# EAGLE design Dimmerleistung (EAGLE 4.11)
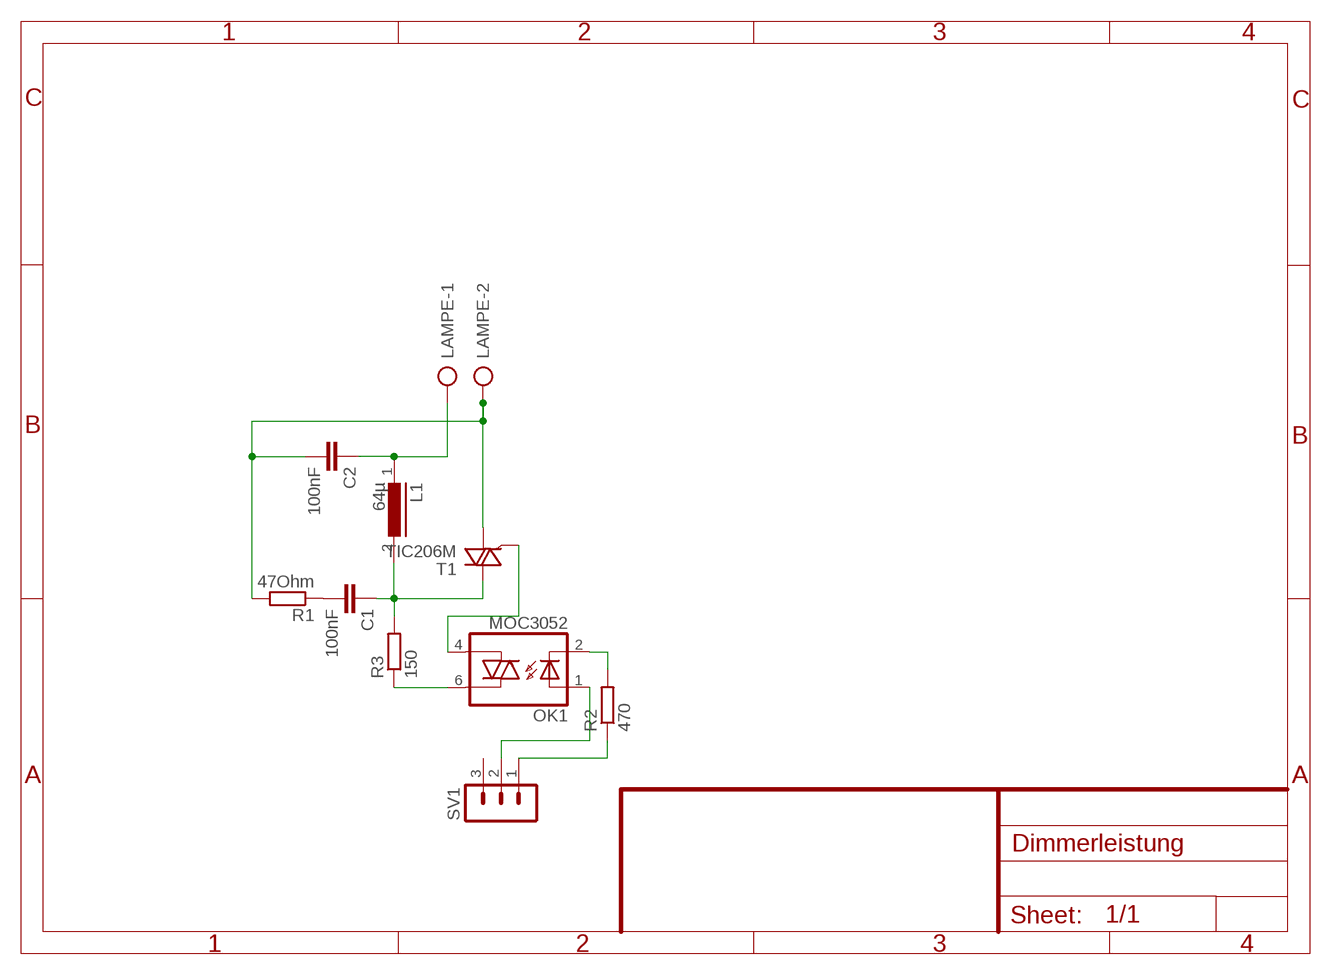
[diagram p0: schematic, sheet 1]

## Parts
C1  100nF  C-EU075-032X103  [C075-032X103]
C2  100nF  C-EU075-032X103  [C075-032X103]
L1  64µ  SFT830D  [SFT830D]
LAMPE  AK300/2  [AK300/2]
OK1  MOC3052  IL420  [DIL06]
R1  47Ohm  R-EU_0207/10  [0207/10]
R2  470  R-EU_0207/10  [0207/10]
R3  150  R-EU_0207/10  [0207/10]
SV1  MA03-1  [MA03-1]
T1  TIC206M  TIC225S  [TO220DS]

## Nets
N$1: OK1.4(A1) T1.G
N$2: C1.2 R1.1
N$3: C1.1 L1.2 R3.2 T1.A2
N$4: C2.1 L1.1 LAMPE.1
N$7: OK1.1(A) SV1.2
N$8: R2.1 SV1.1
N$9: OK1.2(C) R2.2
N$10: OK1.6(A2) R3.1
N$11: C2.2 LAMPE.2 R1.2 T1.A1
Unconnected: SV1.3

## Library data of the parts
C1 C2 = rcl:C-EU: CAPACITOR, European symbol
L1 = inductors:SFT830D: INDUCTOR
LAMPE = con-ptr500:AK300/2: CONNECTOR
OK1 = optocoupler:IL420: SIEMENS OPTO COUPLER
R1-R3 = rcl:R-EU_: RESISTOR, European symbol
SV1 = con-lstb:MA03-1: PIN HEADER
T1 = triac:TIC225S: TRIAC

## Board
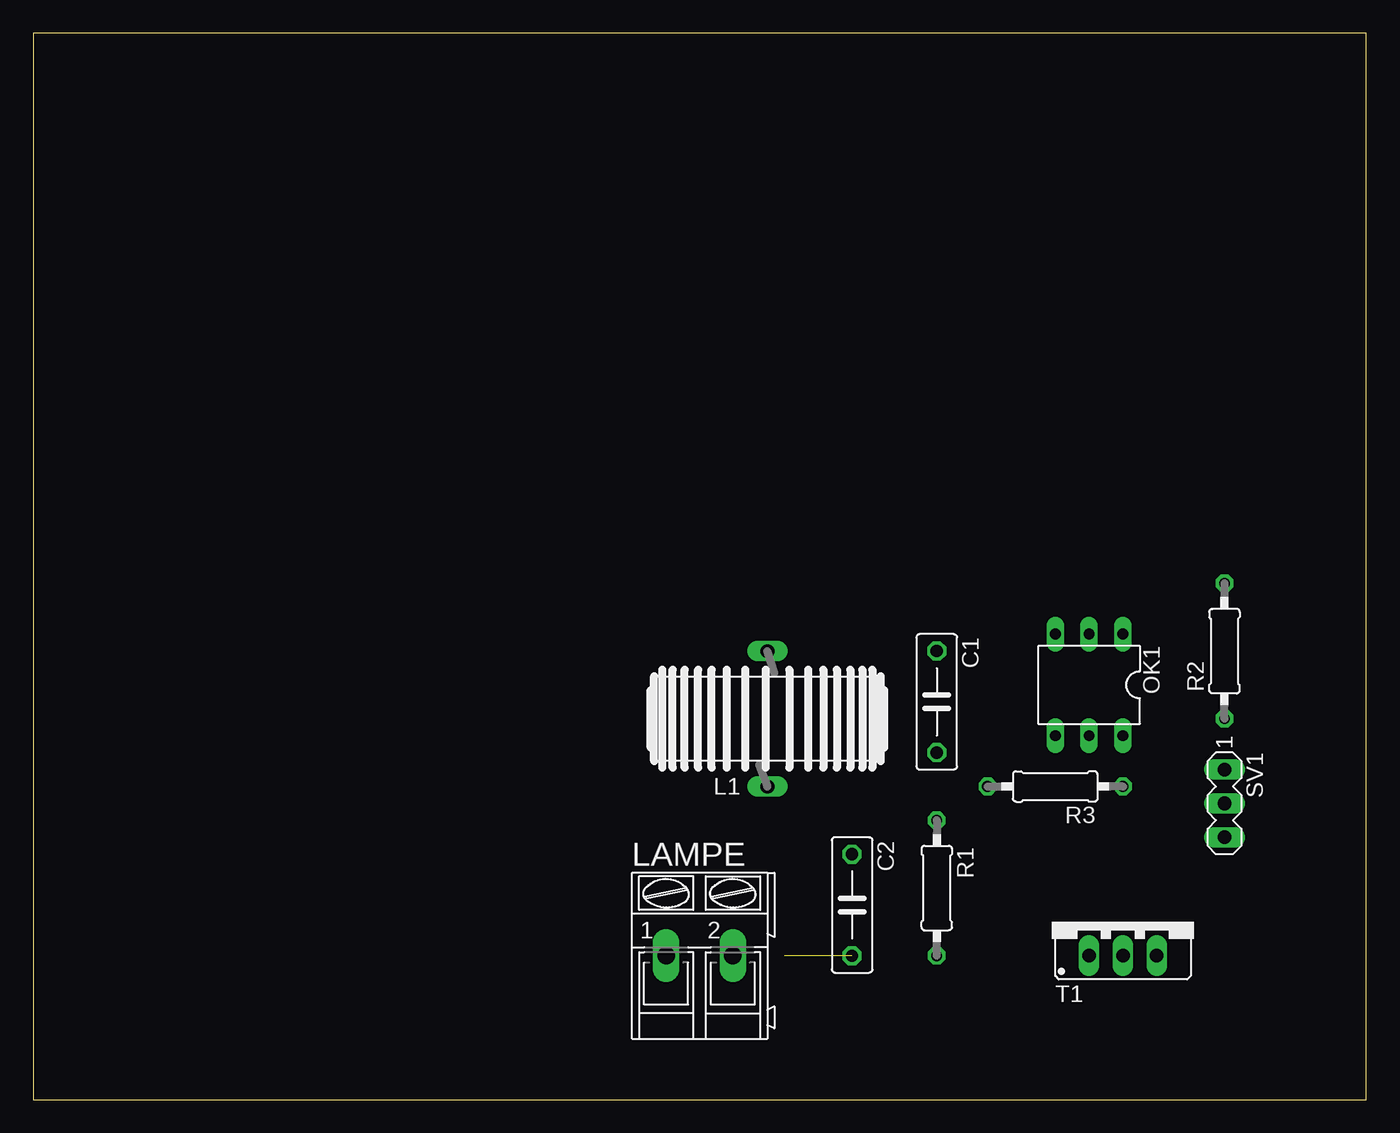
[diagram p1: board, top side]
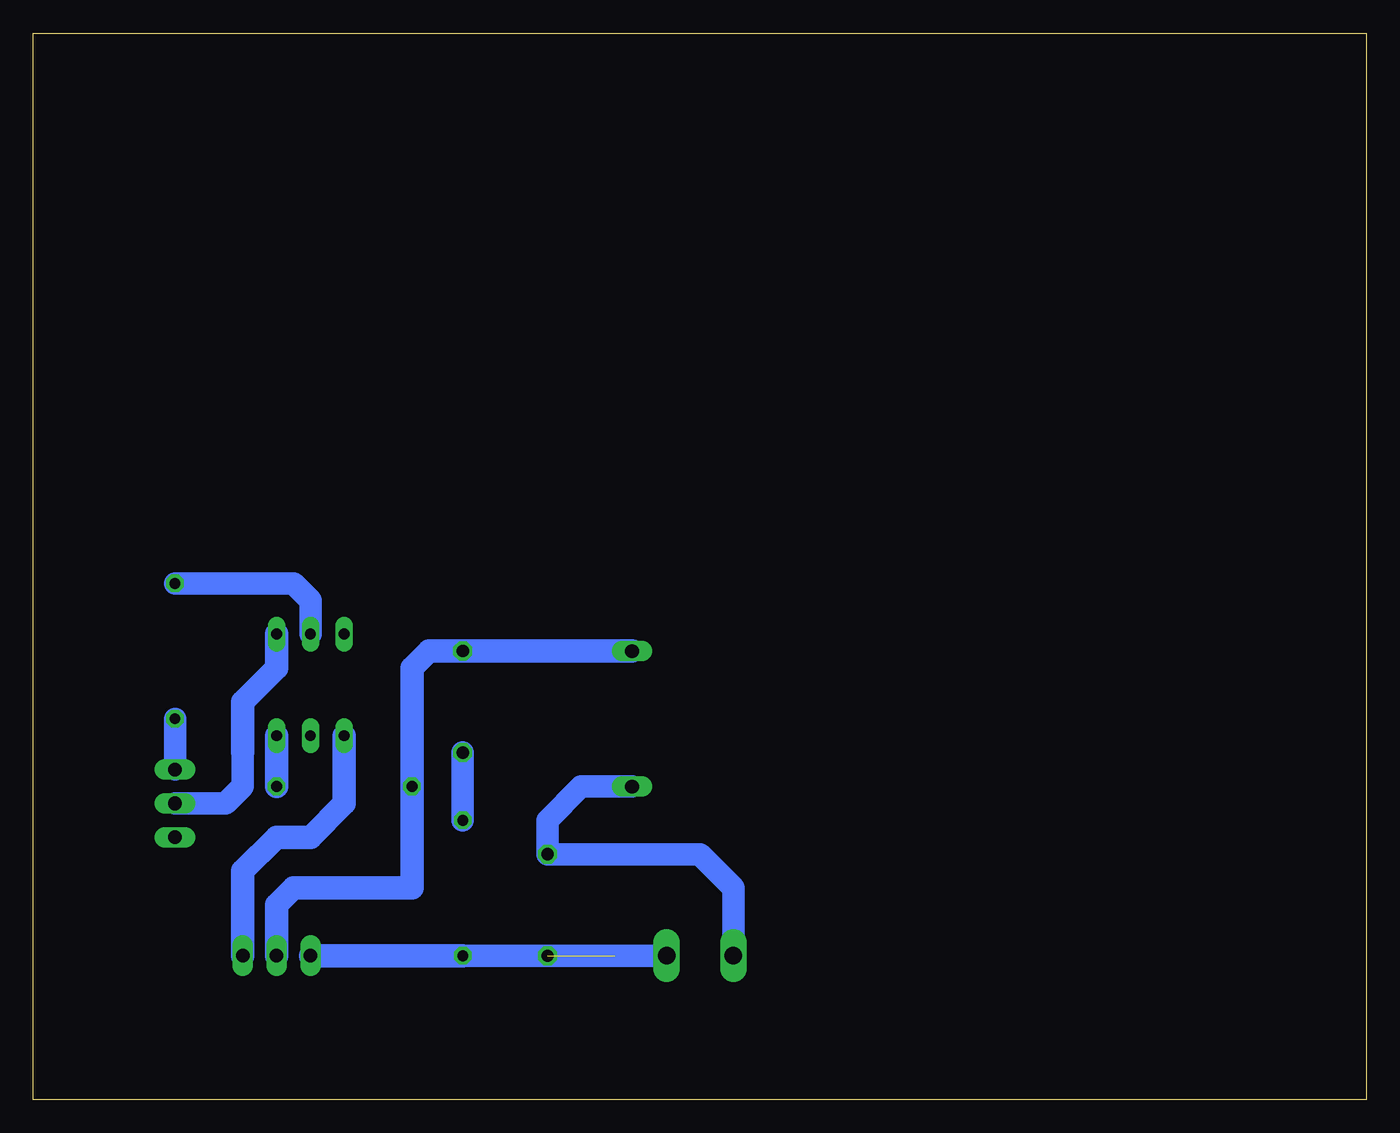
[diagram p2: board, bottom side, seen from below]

Size 100 x 80 mm. Coordinates in mm from the lower left corner, seen from the top.
Outline: 0,0 100,0 100,80 0,80 0,0
Copper layers (1*16): Top 0.035mm / dielectric 1.5mm / Bottom 0.035mm
Design rules "default": minimum track width 10mil, minimum drill 24mil, track to track 8mil, track to pad 8mil, pad to pad 8mil, via to via 8mil, smd to smd 8mil, copper to edge 40mil, drill to drill 8mil, minimum pad ring 10mil, minimum via ring 8mil, stop-mask expansion 4mil, vias tented up to drill 0mil, thermal gap 10mil

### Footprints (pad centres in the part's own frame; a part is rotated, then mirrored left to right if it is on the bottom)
C075-032X103 = drill 0.914 octagon: 1 -3.81,0; 2 3.81,0
SFT830D = drill 1.016 long: 1 -5.08,0; 2 5.08,0
AK300/2 = drill 1.321 long: 1 -2.515,0; 2 2.489,0
DIL06 = drill 0.813 long: 1 -2.54,-3.81; 2 0,-3.81; 3 2.54,-3.81; 4 2.54,3.81; 5 0,3.81; 6 -2.54,3.81
0207/10 = drill 0.813 octagon: 1 -5.08,0; 2 5.08,0
MA03-1 = drill 1.016 long: 1 -2.54,0; 2 0,0; 3 2.54,0
TO220DS = drill 1.016 long: A1 -2.54,-2.54; A2 0,-2.54; G 2.54,-2.54

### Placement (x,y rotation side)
C1  67.78,29.84 270 top
C2  61.43,14.6 270 top
L1  55.08,28.57 90 top
LAMPE  50,10.79 0 top
OK1  79.21,31.11 180 top
R1  67.78,15.87 270 top
R2  89.37,33.65 90 top
R3  76.67,23.49 180 top
SV1  89.37,22.22 270 top
T1  81.75,13.33 0 top

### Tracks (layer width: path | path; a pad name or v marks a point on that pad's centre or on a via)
N$1
  Bottom 1.778: OK1.4 76.67,22.22 79.21,19.68 81.75,19.68 84.29,17.14 T1.G
N$2
  Bottom 1.676: C1.2 R1.1
N$3
  Bottom 1.778: L1.2 C1.1 70.32,33.65 71.59,32.38 71.59,22.22 | 71.59,22.22 71.59,15.87 80.48,15.87 81.75,14.6 T1.A2 | 71.59,22.22 R3.2
N$4
  Bottom 1.676: LAMPE.1 47.46,10.79 47.46,15.87 50,18.41 C2.1 61.43,20.95 58.89,23.49 L1.1
N$7
  Bottom 1.676: 84.29,26.03 84.29,23.49 85.56,22.22 SV1.2
  Bottom 1.778: OK1.1 81.75,32.38 84.29,29.84 84.29,26.03
N$8
  Bottom 1.676: SV1.1 R2.1
N$9
  Bottom 1.676: OK1.2 79.21,37.46 80.48,38.73 R2.2
N$10
  Bottom 1.778: OK1.6 R3.1
N$11  (1 unrouted)
  Bottom 1.676: LAMPE.2 C2.2 R1.2
  Bottom 1.778: R1.2 T1.A1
